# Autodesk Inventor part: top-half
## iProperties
Author: Administrator
Created: 2001-03
Part Number: top-half
Document SubType Name: Modeling
Designer: Administrator
Control State: 0
Master: False
Checked Out: False
PropertySet Name: Design Tracking Control
Shininess: 20.0
PropertySet Name: _Private Model Information
Density: 0.0
Volumn: 0.0
Area: 0.0
PropertySet Name: Model Information
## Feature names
1. Extrusion1
2. Extrusion2
3. Shell1
4. Extrusion4
